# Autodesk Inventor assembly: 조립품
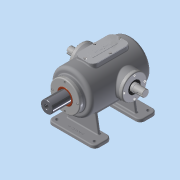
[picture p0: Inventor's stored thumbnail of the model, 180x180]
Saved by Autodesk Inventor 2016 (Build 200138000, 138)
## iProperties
Created: 2018-11
Part Number: 조립품
Material: 일반
Document SubType Name: Assembly
Designer: user
Author: user
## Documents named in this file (15)
- C:\Users\user\Desktop\381121V1011\조립품.iam
- C:\Users\user\Desktop\381121V1011\가변스프링.ipt
- C:\Users\user\Desktop\381121V1011\베어링 6205.ipt
- 베어링 6205.ipt
- C:\Users\user\Desktop\381121V1011\본체.ipt
- C:\Users\user\Desktop\381121V1011\볼트 M4x0.7.ipt
- C:\Users\user\Desktop\381121V1011\부시.ipt
- C:\Users\user\Desktop\381121V1011\상부커버.ipt
- C:\Users\user\Desktop\381121V1011\슬라이드 커버.ipt
- C:\Users\user\Desktop\381121V1011\슬라이드.ipt
- C:\Users\user\Desktop\381121V1011\오일실.ipt
- 오일실.ipt
- C:\Users\user\Desktop\381121V1011\육각머리볼트 M4.ipt
- C:\Users\user\Desktop\381121V1011\축 커버.ipt
- C:\Users\user\Desktop\381121V1011\편심축.ipt
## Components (13 placed, 2 different names)
1. 가변스프링:1
2. M4x0.7:2
3. M4x0.7:3
4. M4x0.7:4
5. M4x0.7:5
6. M4x0.7:1
7. M4x0.7:6
8. M4x0.7:7
9. M4x0.7:8
10. M4x0.7:9
11. M4x0.7:10
12. M4x0.7:11
13. M4x0.7:12
